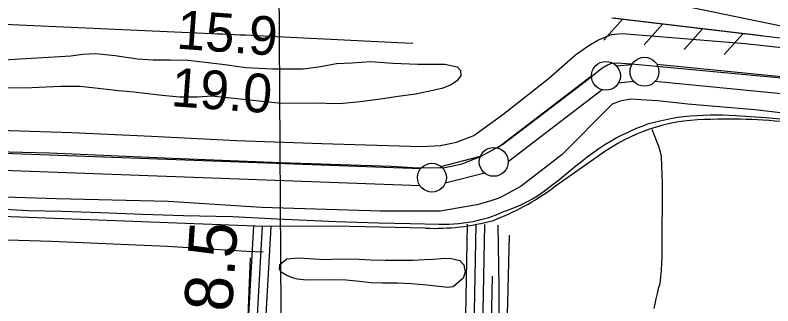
# Model space of a CAD drawing. Extents: x 3508733 to 3546731, y 546897 to 572481.
# Drawn here: x 3522934 to 3524246, y 562982 to 563485 of the extents above; entities that cross this region are included whole.
import ezdxf

# ---------------------------------------------------------------- set-up
doc = ezdxf.new("R2010")
doc.units = 0
for name, color, linetype in [('V-DTCH-CNTR', 7, 'Continuous'), ('V-FLOD-BASE', 7, 'Continuous'), ('V-GRID-MAJR', 7, 'Continuous'), ('V-LEVE-TOET', 7, 'Continuous'), ('V-RIVR-RANG', 7, 'Continuous'), ('V-RIVR-RANG-IDEN', 7, 'Continuous'), ('V-ROAD-CNTR', 7, 'Continuous'), ('V-RRAP-FSHR', 7, 'Continuous'), ('V-SITE-VEGE', 7, 'Continuous'), ('V-SURV-LINE', 7, 'Continuous'), ('V-TOPO-MINR', 7, 'Continuous'), ('V-TOPO-SHOR', 7, 'Continuous')]:
    doc.layers.add(name, color=color, linetype=linetype)

msp = doc.modelspace()

# ---------------------------------------------------------------- linework, layer by layer
at = {"layer": 'V-DTCH-CNTR'}
for points in [[(3521910.972, 563109.215), (3521959.048, 563119.713), (3521969.59, 563121.155), (3521980.163, 563122.341), (3521990.762, 563123.2710000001), (3522001.381, 563123.9400000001), (3522012.012, 563124.354), (3522022.649, 563124.51), (3522118.954, 563124.192), (3522259.846, 563122.576), (3522372.474, 563117.336), (3522504.447, 563112.465), (3522636.599, 563106.014), (3522843.143, 563098.709), (3522996.233, 563093.792), (3523197.042, 563085.368), (3523334.495, 563076.685), (3523363.1, 563075.567)], [(3523769.21, 563121.333), (3523771.344, 563014.85), (3523770.7830000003, 562828.402), (3523761.45, 562634.747), (3523754.514, 562426.25), (3523750.532, 562268.878), (3523745.56, 562093.7390000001), (3523745.541, 561937.503), (3523736.889, 561717.177), (3523731.668, 561503.327), (3523721.076, 561234.435), (3523718.383, 561092.111)]]:
    msp.add_lwpolyline(points, dxfattribs=at)
at = {"layer": 'V-FLOD-BASE'}
msp.add_lwpolyline([(3522115.546, 563277.872), (3522271.42, 563271.699), (3522469.555, 563264.527), (3522621.5810000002, 563259.946), (3522783.1, 563251.647), (3522993.114, 563246.401), (3523205.406, 563237.518), (3523393.228, 563230.207), (3523584.9250000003, 563223.365), (3523621.5, 563221.14), (3523649.847, 563220.559), (3523677.951, 563221.265), (3523707.924, 563227.6240000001), (3523740.813, 563240.908), (3523777.65, 563261.363), (3523850.1920000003, 563316.207), (3523926.128, 563374.362), (3523949.545, 563393.424), (3523959.146, 563398.985), (3523966.656, 563401.991), (3523975.683, 563402.661), (3524001.179, 563400.564), (3524167.511, 563384.993), (3524316.6, 563371.425)], dxfattribs=at)
at = {"layer": 'V-GRID-MAJR'}
msp.add_spline([(3523465.4050000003, 552368.1680000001), (3523424.875, 558426.011), (3523384.323, 564486.938), (3523343.771, 570547.883), (3523343.75, 570550.9500000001)], degree=3, dxfattribs=at)
at = {"layer": 'V-LEVE-TOET'}
for points in [[(3522868.8740000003, 563286.881), (3523031.447, 563281.636), (3523169.847, 563275.632), (3523317.065, 563268.226), (3523464.566, 563262.895), (3523636.492, 563257.804), (3523670.286, 563259.493), (3523698.151, 563265.408), (3523728.1580000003, 563276.754), (3523777.933, 563312.813), (3523856.58, 563374.5210000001), (3523903.819, 563416.0650000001), (3523926.869, 563432.427), (3523942.561, 563441.599), (3523966.054, 563451.203), (3523985.043, 563453.322), (3524041.879, 563448.253), (3524197.613, 563435.814), (3524350.9590000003, 563418.983)], [(3524430.233, 563295.583), (3524214.6380000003, 563321.181), (3524098.361, 563330.829), (3524046.204, 563336.365), (3524017.393, 563338.513), (3523999.215, 563339.243), (3523981.512, 563336.068), (3523967.682, 563330.772), (3523880.693, 563243.959), (3523850.54, 563219.885), (3523809.92, 563189.177), (3523772.794, 563168.8200000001), (3523755.325, 563163.305), (3523733.165, 563156.545), (3523669.651, 563145.584), (3523565.989, 563145.475), (3523360.308, 563151.9940000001), (3523198.576, 563162.424), (3523005.343, 563167.241), (3522823.81, 563172.703)]]:
    msp.add_lwpolyline(points, dxfattribs=at)
at = {"layer": 'V-ROAD-CNTR'}
for points in [[(3524036.1604818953, 563287.394324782), (3524045.383, 563263.892), (3524047.537, 563258.101), (3524049.399, 563252.207), (3524050.964, 563246.228), (3524052.225, 563240.179), (3524054.066, 563194.111), (3524053.7290000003, 563078.505), (3524053.384, 563066.832), (3524052.827, 563055.164), (3524052.061, 563043.509), (3524051.085, 563031.87), (3524049.899, 563020.252), (3524047.41, 563011.6630000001), (3524045.131, 563003.0160000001), (3524043.06, 562994.316), (3524041.199, 562985.569), (3524039.751, 562977.512)], [(3523486.771988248, 563119.5787344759), (3523364.630232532, 563119.4057348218), (3522668.4456249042, 563145.932681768), (3522135.829690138, 563169.0396355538), (3521909.5001427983, 563175.703622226), (3521163.8226341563, 563208.5395565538), (3520567.859826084, 563230.0155136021), (3520131.296699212, 563241.1474913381), (3519612.861736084, 563269.2894350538)], [(3523956.4940488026, 563250.0504735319), (3523865.1502314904, 563186.0636015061)], [(3523323.173315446, 562536.2639011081), (3523329.16630346, 562802.1743692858), (3523347.1062675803, 563120.34673294)], [(3523338.169285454, 562535.925901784), (3523344.1562734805, 562801.5833704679), (3523362.0822376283, 563119.5027346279)], [(3523362.7662362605, 562865.1792432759), (3523377.058207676, 563118.658736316)], [(3523644.2536732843, 563116.29674104), (3523486.771988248, 563119.5787344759)], [(3523731.497498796, 563122.7587281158), (3523723.90551398, 562732.1775092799), (3523713.396534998, 562455.212063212), (3523651.594658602, 562352.09826944)], [(3523746.494468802, 563122.4667287), (3523738.8994839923, 562731.74751014), (3523728.239505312, 562450.800072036), (3523664.46063287, 562344.3872848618)], [(3523716.50052879, 563123.0507275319), (3523710.976539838, 562838.8772958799)]]:
    msp.add_lwpolyline(points, dxfattribs=at)
for centre, radius, start, end in [((3524135.6460665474, 562982.9873784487), 321.58691228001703, 89.34636780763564, 123.85461225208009), ((3524170.1130550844, 562377.5867893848), 927.4766276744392, 82.07900403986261, 91.82810403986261), ((3523602.343534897, 563545.3253147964), 445.1250817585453, 290.97538708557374, 306.18618986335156), ((3523659.221413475, 563506.3718735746), 390.36219363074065, 267.8025522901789, 285.2172245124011)]:
    msp.add_arc(centre, radius, start, end, dxfattribs=at)
at = {"layer": 'V-RRAP-FSHR'}
for p, q in [((3523985.667, 563478.2660000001), (3523953.12, 563441.862)), ((3524055.174, 563469.979), (3524022.628, 563433.576)), ((3524124.682, 563461.693), (3524092.136, 563425.29)), ((3524194.19, 563453.407), (3524161.644, 563417.003))]:
    msp.add_line(p, q, dxfattribs=at)
for points in [[(3523475.5105324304, 563626.122248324), (3524086.4289329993, 563502.3513682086), (3525193.2541500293, 563274.5523279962), (3526957.4668876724, 562942.6186316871), (3528202.595592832, 562690.3746634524), (3529085.8590816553, 562552.3312713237), (3529836.463370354, 562463.4030152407), (3529988.494602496, 562444.0965192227), (3530121.4241386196, 562433.2830792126), (3530591.9418990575, 562422.0989512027), (3531229.943051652, 562384.227335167)], [(3523966.701, 563480.527), (3524928.774, 563365.833), (3525288.366, 563305.357), (3525871.313, 563221.935)], [(3523969.24, 563480.224), (3524226.4020000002, 563449.566)]]:
    msp.add_lwpolyline(points, dxfattribs=at)
at = {"layer": 'V-SITE-VEGE'}
msp.add_lwpolyline([(3522913.298, 563407.791), (3523029.884, 563414.339), (3523050.426, 563417.652), (3523072.909, 563418.381), (3523106.582, 563415.035), (3523145.35, 563409.069), (3523172.343, 563407.576), (3523201.918, 563407.828), (3523232.466, 563407.085), (3523257.863, 563404.031), (3523296.648, 563399.448), (3523333.0640000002, 563394.495), (3523378.972, 563392.194), (3523432.396, 563391.974), (3523462.606, 563396.161), (3523490.262, 563400.969), (3523516.106, 563402.448), (3523549.447, 563404.627), (3523587.86, 563401.819), (3523631.017, 563400.34), (3523677.937, 563400.193), (3523698.781, 563395.618), (3523704.815, 563388.845), (3523705.304, 563379.9670000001), (3523698.501, 563371.1730000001), (3523688.369, 563364.392), (3523672.522, 563358.068), (3523648.612, 563353.019), (3523626.667, 563347.949), (3523596.6580000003, 563343.955), (3523570.198, 563340.316), (3523530.907, 563335.05), (3523495.97, 563331.509), (3523447.682, 563332.654), (3523394.451, 563332.279), (3523273.936, 563344.508), (3523249.08, 563343.216), (3523218.523, 563343.175), (3523188.3910000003, 563345.884), (3523163.3850000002, 563348.536), (3523139.366, 563351.375), (3523113.373, 563354.039), (3523046.031, 563361.318), (3523012.72, 563361.701), (3522962.224, 563359.323), (3522871.326, 563358.002)], dxfattribs=at)
msp.add_lwpolyline([(3523391.975, 563053.4990000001), (3523404.142, 563063.438), (3523424.909, 563064.978), (3523450.779, 563063.297), (3523471.116, 563061.88), (3523492.671, 563063.211), (3523528.826, 563062.599), (3523549.3680000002, 563061.573), (3523574.6520000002, 563060.6900000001), (3523622.676, 563060.93), (3523642.449, 563062.083), (3523658.071, 563062.894), (3523671.322, 563063.928), (3523686.346, 563064.348), (3523703.693, 563060.5920000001), (3523710.326, 563053.006), (3523713.142, 563040.128), (3523709.47, 563030.093), (3523692.1010000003, 563014.876), (3523682.801, 563013.799), (3523646.289, 563017.973), (3523620.032, 563020.054), (3523595.74, 563021.321), (3523569.454, 563021.028), (3523549.699, 563021.651), (3523530.161, 563023.853), (3523507.066, 563026.093), (3523480.2, 563026.9940000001), (3523437.903, 563026.492), (3523422.512, 563028.25), (3523414.036, 563030.126), (3523404.005, 563034.193), (3523394.387, 563040.034), (3523391.289, 563045.406)], close=True, dxfattribs=at)
at = {"layer": 'V-SURV-LINE'}
for points in [[(3523974.960480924, 563396.9232993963), (3524001.9213939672, 563399.7866735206)], [(3524044.723492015, 563399.9591097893), (3524499.918800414, 563355.3089465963)], [(3523769.0621981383, 563255.0901221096), (3523931.696083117, 563379.6529064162)], [(3524005.101978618, 563369.9557494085), (3523978.1416300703, 563367.0924352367)], [(3524496.9840291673, 563325.4528390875), (3524041.7877784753, 563370.1030947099)], [(3523949.938457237, 563355.8366139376), (3523787.3048629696, 563231.2740522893)], [(3520197.438594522, 563346.0482176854), (3523635.9648644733, 563219.4589295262)], [(3523634.847282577, 563189.479750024), (3520196.3206543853, 563316.0690513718)], [(3523671.027869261, 563223.2089779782), (3523739.255826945, 563240.6239000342)], [(3523746.668037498, 563211.5539982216), (3523678.440187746, 563194.139103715)]]:
    msp.add_lwpolyline(points, dxfattribs=at)
for centre in [(3523956.6854000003, 563379.8975899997), (3524023.3773700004, 563386.9811199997), (3523762.3155600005, 563231.0290499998), (3523655.3804200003, 563203.7338699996)]:
    msp.add_circle(centre, 25, dxfattribs=at)
at = {"layer": 'V-TOPO-MINR'}
msp.add_lwpolyline([(3521684.4459631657, 563528.2814152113), (3522034.0759665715, 563509.2589509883), (3522061.7763978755, 563507.791734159), (3522089.4794606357, 563506.3775624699), (3522117.1864705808, 563505.0429584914), (3522144.896111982, 563503.7613996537), (3523273.67820018, 563453.1799918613), (3523283.5120868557, 563452.7425699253), (3523293.346162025, 563452.309460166), (3523303.180519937, 563451.8828186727), (3523313.0150663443, 563451.4604893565), (3523322.8493434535, 563451.032401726), (3523332.683073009, 563450.5923242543), (3523342.5159812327, 563450.1342620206), (3523352.348341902, 563449.6642099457), (3523596.3921165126, 563437.7736049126), (3523622.2033776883, 563436.4709392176)], dxfattribs=at)
at = {"layer": 'V-TOPO-SHOR'}
for points in [[(3523965.507, 563267.7000000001), (3523974.536, 563272.474), (3523983.66, 563277.061), (3523992.878, 563281.462), (3524002.182, 563285.675), (3524011.5700000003, 563289.697), (3524021.038, 563293.527), (3524030.582, 563297.162), (3524040.65, 563299.823), (3524050.775, 563302.264), (3524060.952, 563304.482), (3524071.173, 563306.479), (3524081.438, 563308.25), (3524091.735, 563309.8), (3524102.901, 563310.7880000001), (3524114.0810000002, 563311.547), (3524125.275, 563312.084), (3524136.48, 563312.3910000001), (3524147.687, 563312.473), (3524158.893, 563312.33), (3524170.094, 563311.957), (3524181.286, 563311.361), (3524207.113, 563309.716), (3524232.924, 563307.845), (3524258.719, 563305.743)], [(3522895.617, 563150.355), (3522955.9960000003, 563146.72), (3523014.444, 563145.655), (3523081.3140000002, 563143.515), (3523154.253, 563140.5210000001), (3523224.852, 563138.336), (3523310.161, 563136.376), (3523387.412, 563132.743), (3523489.363, 563127.844), (3523562.514, 563125.827), (3523617.423, 563124.215), (3523667.627, 563123.049), (3523676.112, 563123.101), (3523684.595, 563123.371), (3523693.065, 563123.867), (3523701.522, 563124.583), (3523709.953, 563125.5210000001), (3523718.36, 563126.681), (3523726.733, 563128.061), (3523733.528, 563129.476), (3523740.278, 563131.0920000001), (3523746.975, 563132.909), (3523753.617, 563134.922), (3523760.197, 563137.129), (3523766.707, 563139.534), (3523773.142, 563142.129), (3523779.4990000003, 563144.914), (3523786.751, 563147.394), (3523793.927, 563150.091), (3523801.018, 563153.004), (3523808.018, 563156.125), (3523814.919, 563159.457), (3523821.721, 563162.9940000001), (3523828.412, 563166.733), (3523834.988, 563170.672), (3523841.441, 563174.807), (3523852.357, 563182.724), (3523863.142, 563190.8200000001), (3523873.793, 563199.088), (3523884.31, 563207.527), (3523894.687, 563216.135), (3523904.341, 563224.1140000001), (3523914.1550000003, 563231.897), (3523924.129, 563239.474), (3523934.254, 563246.8470000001), (3523944.529, 563254.011), (3523954.947, 563260.962), (3523965.507, 563267.7000000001)], [(3523776.2290000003, 562648.247), (3523778.232, 562737.286), (3523786.596, 562987.308), (3523789.506, 563103.997)], [(3523340.343, 563065.058), (3523330.852, 562819.007), (3523323.184, 562560.785), (3523314.3510000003, 562320.803), (3523312.623, 562118.956), (3523309.883, 562033.929), (3523304.679, 561887.979), (3523297.6950000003, 561672.277), (3523296.188, 561541.178), (3523288.37, 561304.1240000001), (3523285.276, 561102.882)], [(3523759.361, 563033.294), (3523756.105, 562868.817), (3523748.177, 562654.971), (3523741.968, 562471.716), (3523739.539, 562289.956), (3523733.0670000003, 562068.909), (3523729.8680000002, 561864.756), (3523720.63, 561641.006), (3523714.4450000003, 561474.852), (3523704.25, 561197.585), (3523698.923, 561120.861)]]:
    msp.add_lwpolyline(points, dxfattribs=at)

# ---------------------------------------------------------------- texts
at = {"layer": 'V-RIVR-RANG'}
for s, p in [('15.9', (3523211.706973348, 563427.1453219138)), ('19.0', (3523202.1140334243, 563327.5783720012))]:
    msp.add_text(s, height=67.0000000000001, rotation=355.86832571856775, dxfattribs=at).set_placement(p)
at = {"layer": 'V-RIVR-RANG-IDEN'}
msp.add_text('R-138.5', height=82.99999799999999, rotation=86.00782020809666, dxfattribs=at).set_placement((3523291.8545738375, 562730.3485596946))

doc.saveas('drawing.dxf')
